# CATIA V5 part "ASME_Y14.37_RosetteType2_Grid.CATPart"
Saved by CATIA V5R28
Part number: 333X3333-303
Revision: --
Nomenclature: ASME_Y14.37_RosetteType2
Bounding box of the stored display mesh (mm): x -188.298 to 149.724, y -714.612 to 664.697, z 0 to 93.163
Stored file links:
  C:\Users\jvl2147\Documents\AP242 testing\Composite Example Parts for PER\Grid Data\ASME_Y14.37_RosetteType2_Grid.CATPart
  \\NW\Data\MSE-Composites\ASME Y14.37\ASME Y-14.37_COMPOSITES.CATMaterial
  C:\Program Files\Dassault Systemes\B28SP3PRALL\win_b64\startup\composites\LaminateColors.txt
  C:\Program Files\Dassault Systemes\B28SP3PRALL\win_b64\startup\composites\DropOffPattern1BackSlash.txt
  C:\Program Files\Dassault Systemes\B28SP3PRALL\win_b64\startup\composites\DropOffPattern1Backslash.txt
  C:\Program Files\Dassault Systemes\B28SP3PRALL\win_b64\startup\composites\DropOffPattern1InverseV.txt
  C:\Program Files\Dassault Systemes\B28SP3PRALL\win_b64\startup\composites\DropOffPattern1InverseW.txt
  C:\Program Files\Dassault Systemes\B28SP3PRALL\win_b64\startup\composites\DropOffPattern1Slash.txt
  C:\Program Files\Dassault Systemes\B28SP3PRALL\win_b64\startup\composites\DropOffPattern1V.txt
  C:\Program Files\Dassault Systemes\B28SP3PRALL\win_b64\startup\composites\DropOffPattern1V_Symetry.txt
  C:\Program Files\Dassault Systemes\B28SP3PRALL\win_b64\startup\composites\DropOffPattern1V_Symetry_2Consecutive.txt
  C:\Program Files\Dassault Systemes\B28SP3PRALL\win_b64\startup\composites\DropOffPattern1W.txt
  C:\Program Files\Dassault Systemes\B28SP3PRALL\win_b64\startup\composites\DropOffPattern2Cross.txt
  C:\Program Files\Dassault Systemes\B28SP3PRALL\win_b64\startup\composites\DropOffPattern2Diamond.txt
  C:\Program Files\Dassault Systemes\B28SP3PRALL\win_b64\startup\composites\DropOffPattern2Socks.txt
  C:\Program Files\Dassault Systemes\B28SP3PRALL\win_b64\startup\composites\DropOffPattern45AfterOthers.txt
  C:\Program Files\Dassault Systemes\B28SP3PRALL\win_b64\startup\composites\DropOffPattern4TwinDiamonds45.txt
  C:\Program Files\Dassault Systemes\B28SP3PRALL\win_b64\startup\composites\DropOffPattern5Cross_Pseudo_Sym.txt
  C:\Program Files\Dassault Systemes\B28SP3PRALL\win_b64\startup\composites\DropOffPattern5Diamond_Pseudo_Sym.txt
  C:\Program Files\Dassault Systemes\B28SP3PRALL\win_b64\startup\composites\DropOffPattern5Socks_Pseudo_Sym.txt
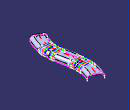
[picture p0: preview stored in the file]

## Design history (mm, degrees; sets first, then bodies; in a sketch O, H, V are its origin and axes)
AxisSystem1 "ROSETTE COORDINATE SYSTEM": origin (-72.9205, -637.9645, 93.98), X (0.5026, 0.8645, 0), Y (-0.8645, 0.5026, 0), Z (0, 0, 1)
CompParametersFeature1 "CATCoParametersFeatName": Value 0, Value 45, Value -45, Value 90
CompEOPGroupFeature1 "CATCoEOPGroupFeatName"
TTRSSet1
CompGridRoot1
CompStacking1 "Stacking"
Set1 "CONSTRUCTION GEOMETRY"
  Set2 "CONSTRUCTION - LAMINATE REFERENCE SURFACE"
    Sketch1 on xy-plane, origin (0, 0, 0), H (1, 0, 0), V (0, 1, 0)
      spline S1 through (-79.505, -649.09) (21.2912, -260.3998) (-51.6257, 228.8061) (37.963, 602.845)
    Plane1: type Normal, Curve Sketch1, RefPoint vertex of Sketch1, Ratio 0
    Sketch2 on Plane1, origin (-464.3095, -417.3341, 0), H (-0.8566, 0.5159, 0), V (0, 0, 1)
      line L1 (-525.4052, 91.6386) -> (-373.0052, 91.6386)
      line L2 (-322.2052, 40.8386) -> (-322.2052, 0)
      line L3 (-576.2052, 0) -> (-576.2052, 40.8386)
      reference projected point E1 (-449.2052, 0) from vertex of Sketch1
      reference projected point E2 (-449.2052, 0) from vertex of Sketch1
      arc A1 centre (-373.0052, 40.8386) radius 50.8 from (-373.0052, 91.6386) to (-322.2052, 40.8386) cw
      arc A2 centre (-525.4052, 40.8386) radius 50.8 from (-576.2052, 40.8386) to (-525.4052, 91.6386) cw
      distance E1 L2 = 127
      distance E2 L3 = 127
      radius A1 = 50.8
      radius A2 = 50.8
      horizontal: L1 H
      vertical: L2 V, L3 V
      tangency: A1 L1, A1 L2, A2 L3, A2 L1
    Sweep1: type Unspec, Profile Sketch2, Guide Sketch1
  Set3 "CONSTRUCTION - PLIES EOPS"
    Plane2: type Normal, Curve Sketch1, RefPoint vertex of Sketch1, Ratio 0
    Plane3: type Normal, Curve Sketch1, RefPoint {point type OnCurve, Support Sketch1, Length 1118.262}, Ratio 0.99
    Plane4: type Normal, Curve Sketch1, Ratio 0.01
    Intersect1: ToIntersect1 Plane3, ToIntersect2 Sweep1
    Intersect2: ToIntersect1 Sweep1, ToIntersect2 Plane4
    Plane5: type Offset, RefPlane xy-plane, Offset 2.54
    Intersect3: ToIntersect1 Plane5, ToIntersect2 Join1
    Near1: MultiElement Intersect3, ReferenceElement edge of Sweep1
    Near2: MultiElement Intersect3, ReferenceElement edge of Sweep1
  Set4 "CONSTRUCTION - ROSETTE COORDINATE SYSTEM"
    Intersect4: ToIntersect1 Plane4, ToIntersect2 Project1
    Line1: type Tangency, RefPoint Intersect4, Curve Project1, Start 0, End 25.4
    Plane6: type Offset, RefPlane xy-plane, Offset 93.98
    Project1 "CURVE": ToProject Sketch1, Support Plane6
  CurvePar1: Offset Near1, Support Join1, Offset2 0, Offset1 50.8
  Set5 "CONSTRUCTION - GRID"
    Point1: type OnCurve, Support Project2, Length 258.5616 {= length(Project2) / 5}
    Plane7: type Normal, Curve Project2, RefPoint Point1
    Point2: type OnCurve, Support Project2, Length 517.1231 {= (length(Project2)) * 2 / 5}
    Plane8: type Normal, Curve Project2, RefPoint Point2
    Point3: type OnCurve, Support Project2, Length 775.6847 {= (length(Project2)) * 3 / 5}
    Plane9: type Normal, Curve Project2, RefPoint Point3
    Point4: type OnCurve, Support Project2, Length 1034.2463 {= (length(Project2)) * 4 / 5}
    Plane10: type Normal, Curve Project2, RefPoint Point4
    Plane11: type Normal, Curve Sketch1, Ratio 0.01
    Plane12: type Normal, Curve Sketch1, RefPoint {point type OnCurve, Support Sketch1, Length 1118.262}, Ratio 0.99
    Sweep2: type Segment, GuideCrv Near1, Length1 10, Length2 10, Angle 90, GuideSurf Join1
    Sweep3: type Segment, GuideCrv Near2, GuideSurf Join1, Length1 10, Length2 10, Angle 90
    CurvePar2: Offset2 0, Offset1 20, Support Join1
    CurvePar3: Offset2 0, Offset1 1, Support Join1
    CurvePar4: Support Join1, Offset2 0, Offset1 1
Set6 "ENGINEERING GEOMETRY"
  Set7 "LAMINATE REFERENCE SURFACE"
    Join1 "LAMINATE REFERENCE SURFACE": Elements Sweep1
  Set8 "GUIDE CURVE - ZERO DEGREE ORIENTATION"
    Project2 "0° GUIDE CURVE": ToProject Sketch1, Support Join1, Direction xy-plane
  Set9 "LLAI - NO DROP OFF ZONE"
    CompStdContourFeature1 "LLAI - NO DROP OFF ZONE BOUNDARY": ClosedSetOfCurves (CurvePar3; {curvepar Support Join1, Offset2 0, Offset1 20}; CurvePar4; CurvePar2), ExtrapolDist 0.2, SupportSurface Join1
    CompGridNoDropOffArea1 "CATCoGridNoDropOffAreaFeatName": NoDropOffContour CompStdContourFeature1
Set10 "Top Surface from Virtual Stackings"
  CompIsoThickAreasTopSurface1 "CATCoIsoThickAreasTopSurfaceFeatName": ListITAs ({datumsurface}; {datumsurface}; {datumsurface}; {datumsurface}; {datumsurface}), ListRampContours ({datumcurve}; {datumcurve}; {datumcurve}; {datumcurve})
Body1 "-303" (main body)
  ThickSurface1: BotOffset 0, Surface CompIsoThickAreasTopSurface1, TopOffset 2
  Split1: SplitPlane Join1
